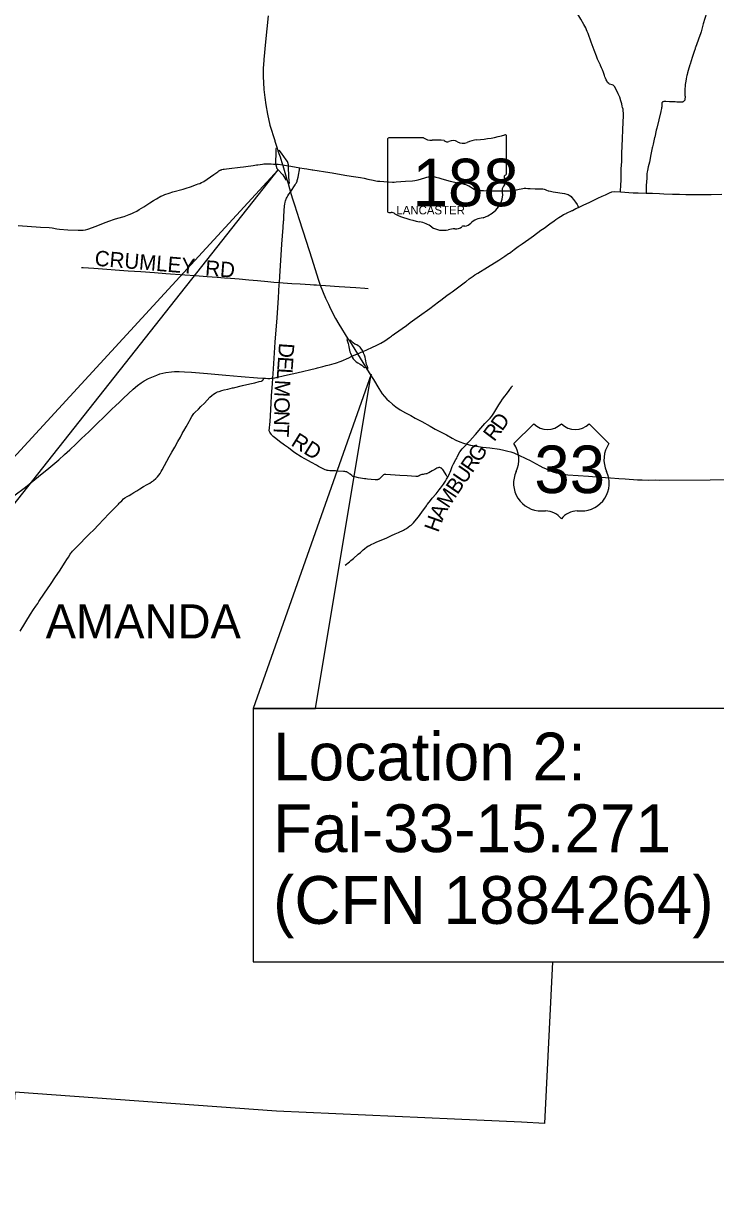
# Model space of a CAD drawing. Extents: x 1761803 to 2441803, y 509895 to 949895.
# Drawn here: x 1904079 to 1944652, y 661208 to 729125 of the extents above; entities that cross this region are included whole.
import ezdxf

# ---------------------------------------------------------------- set-up
doc = ezdxf.new("R2010")
doc.units = 0
for name, color, linetype in [('GM_X_County', 7, 'Continuous'), ('GM_X_County_Road', 7, 'Continuous'), ('GM_X_County_Road_Text', 7, 'Continuous'), ('GM_X_Minor_Lake', 7, 'Continuous'), ('GM_X_Minor_River_Text', 7, 'Continuous'), ('GM_X_State_Location', 7, 'Continuous'), ('GM_X_Township_Road', 7, 'Continuous'), ('GM_X_US_Location', 7, 'Continuous')]:
    doc.layers.add(name, color=color, linetype=linetype)

msp = doc.modelspace()

# ---------------------------------------------------------------- linework, layer by layer
at = {"layer": 'GM_X_County'}
msp.add_lwpolyline([(1935079, 674149), (1934625, 664674), (1933260, 664759), (1929353, 664934), (1918913, 665413), (1903591, 666509), (1903235, 661208)], dxfattribs=at)
at = {"layer": 'GM_X_County_Road'}
for points in [[(1919338, 717595), (1919345, 717702), (1919351, 717796), (1919373, 718129), (1919394, 718424), (1919403, 718522), (1919420, 718635), (1919445, 718730), (1919461, 718776), (1919480, 718821), (1919507, 718881), (1919539, 718938), (1919581, 719008), (1919645, 719104), (1919733, 719238), (1919934, 719542), (1920014, 719666), (1920057, 719737), (1920080, 719780), (1920120, 719871), (1920137, 719918), (1920150, 719965), (1920182, 720110), (1920281, 720657)], [(1928945, 702538), (1928918, 702572), (1928899, 702598), (1928857, 702668), (1928691, 702929), (1928654, 702983), (1928634, 703009), (1928611, 703033), (1928585, 703055), (1928572, 703064), (1928557, 703073), (1928527, 703087), (1928494, 703096), (1928461, 703099), (1928444, 703099), (1928428, 703097), (1928395, 703090), (1928363, 703080), (1928317, 703061), (1928258, 703032), (1928187, 702993), (1928032, 702900), (1927933, 702842), (1927833, 702787), (1927747, 702745), (1927724, 702736), (1927696, 702729), (1927663, 702723), (1927570, 702710), (1927503, 702701), (1927426, 702686), (1927368, 702664), (1927331, 702647), (1927267, 702614), (1927212, 702591), (1927190, 702584), (1927171, 702581), (1927149, 702579), (1927071, 702580), (1926581, 702607), (1926139, 702637), (1925861, 702658), (1925321, 702694), (1925272, 702696), (1925255, 702695), (1925238, 702693), (1925222, 702688), (1925193, 702676), (1925166, 702651), (1925130, 702617), (1925051, 702533), (1924994, 702475), (1924958, 702442), (1924932, 702422), (1924919, 702414), (1924905, 702406), (1924890, 702400), (1924875, 702395), (1924859, 702391), (1924843, 702389), (1924811, 702386), (1924779, 702386), (1924697, 702390), (1924468, 702406), (1924256, 702422), (1924159, 702432), (1924078, 702443), (1923723, 702507), (1923498, 702549), (1923451, 702560), (1923422, 702569), (1923402, 702576), (1923384, 702585), (1923366, 702596), (1923325, 702629), (1923233, 702711), (1923202, 702738), (1923164, 702769), (1923124, 702798), (1923096, 702815), (1923066, 702829), (1923035, 702841), (1923003, 702850), (1922970, 702857), (1922921, 702864), (1922839, 702872), (1922529, 702896), (1922381, 702905), (1922271, 702908), (1922152, 702911), (1922038, 702917), (1921940, 702925), (1921881, 702933), (1921844, 702942), (1921768, 702969), (1921579, 703068), (1921385, 703165), (1921253, 703234), (1920965, 703394), (1920785, 703497), (1920357, 703735), (1920215, 703816), (1920146, 703860), (1920000, 703965), (1919842, 704079), (1919612, 704253), (1919379, 704418), (1919093, 704634), (1918877, 704802), (1918713, 704927), (1918665, 704973), (1918637, 705002), (1918615, 705029), (1918568, 705105), (1918532, 705175), (1918493, 705250), (1918539, 705796), (1918562, 706136), (1918605, 706872), (1918625, 707298), (1918678, 708032), (1918699, 708334), (1918732, 708884), (1918753, 709186), (1918847, 710445), (1918948, 711872), (1919032, 713032), (1919080, 713829), (1919088, 713938), (1919113, 714284), (1919239, 716183), (1919307, 717164), (1919333, 717524), (1919338, 717595)], [(1907498, 714821), (1907511, 714822), (1907536, 714822), (1907587, 714821), (1908215, 714776), (1910225, 714627), (1910979, 714573), (1911774, 714517), (1912436, 714472), (1913556, 714396), (1914161, 714352), (1914863, 714293), (1915440, 714253), (1915874, 714219), (1916221, 714195), (1916727, 714149), (1917296, 714096), (1917801, 714053), (1918406, 713999), (1918764, 713966), (1919088, 713938), (1919302, 713922), (1919809, 713888), (1920299, 713858), (1920595, 713840), (1920888, 713819), (1921097, 713806)], [(1921097, 713806), (1921252, 713796), (1921478, 713782), (1921784, 713763)], [(1921784, 713763), (1922587, 713712), (1923567, 713641), (1924083, 713599), (1924283, 713581)], [(1930581, 705043), (1930893, 705401), (1931131, 705671), (1931428, 706000), (1931522, 706114), (1931641, 706292), (1931874, 706668), (1931943, 706780), (1932061, 706957), (1932165, 707104), (1932302, 707288), (1932381, 707393), (1932545, 707616), (1932681, 707801), (1932711, 707840), (1932732, 707863), (1932766, 707894)], [(1929423, 703567), (1929472, 703658), (1929510, 703733), (1929663, 704015), (1929803, 704191), (1929941, 704346), (1930060, 704473), (1930132, 704557), (1930235, 704672), (1930399, 704836), (1930557, 705015), (1930581, 705043)], [(1922946, 697377), (1923196, 697583), (1923278, 697650), (1923423, 697772), (1923706, 698022), (1923831, 698129), (1923990, 698271), (1924077, 698346), (1924205, 698447), (1924316, 698517), (1924365, 698544), (1924431, 698578), (1924509, 698614), (1924595, 698653), (1924804, 698744), (1925044, 698846), (1925380, 698988), (1925662, 699111), (1925877, 699209), (1926072, 699298), (1926350, 699431), (1926423, 699469), (1926535, 699538), (1926629, 699604), (1926735, 699682), (1926800, 699733), (1926897, 699822), (1926942, 699869), (1927018, 699955), (1927228, 700208), (1927436, 700483), (1927697, 700861), (1927746, 700927), (1927852, 701064), (1927938, 701173), (1928040, 701301), (1928261, 701565), (1928437, 701786), (1928527, 701898), (1928702, 702136), (1928776, 702245), (1928811, 702301), (1928877, 702414), (1928945, 702538), (1929007, 702660), (1929050, 702755), (1929082, 702825), (1929127, 702930), (1929217, 703159), (1929250, 703233), (1929293, 703327), (1929423, 703567)]]:
    msp.add_lwpolyline(points, dxfattribs=at)
at = {"layer": 'GM_X_County_Road_Text'}
for p, q in [((1933982, 705665), (1932822, 704504)), ((1938391, 704504), (1937231, 705665)), ((1934446, 700560), (1934679, 700560)), ((1936535, 700560), (1936767, 700560))]:
    msp.add_line(p, q, dxfattribs=at)
for centre, radius, start, end in [((1934795, 706493), 1160, 225.573, 314.427), ((1936419, 706493), 1160, 225.573, 314.427), ((1931492, 703573), 1624, 334.54712, 35.00093), ((1939721, 703573), 1624, 144.99907, 205.45288), ((1934428, 702184), 1624, 154.83192, 270.63826), ((1936785, 702184), 1624, 269.36174, 25.16808), ((1934679, 699400), 1160, 36.8699, 90), ((1936535, 699400), 1160, 90, 143.1301)]:
    msp.add_arc(centre, radius, start, end, dxfattribs=at)
at = {"layer": 'GM_X_Minor_Lake'}
for points in [[(1944280, 730414), (1944229, 730220), (1944097, 729708), (1943914, 729080), (1943789, 728628), (1943751, 728500), (1943717, 728407), (1943533, 727911), (1943457, 727699), (1943451, 727680)], [(1937895, 726660), (1937859, 726740), (1937824, 726819), (1937729, 727027), (1937655, 727193), (1937523, 727538), (1937466, 727705), (1937355, 728009), (1937170, 728513), (1937121, 728642), (1937079, 728734), (1937028, 728851), (1936925, 729051), (1936754, 729363), (1936573, 729655), (1936402, 729942)], [(1943434, 727630), (1943377, 727465), (1943270, 727111), (1943147, 726721)], [(1943451, 727680), (1943434, 727630)], [(1943147, 726721), (1943135, 726684), (1943031, 726356), (1942989, 726216), (1942964, 726130), (1942950, 726066), (1942931, 725979), (1942908, 725870), (1942888, 725739), (1942874, 725641), (1942864, 725540)], [(1938264, 725742), (1938263, 725744), (1938234, 725802), (1938188, 725909), (1938156, 725982), (1938128, 726059), (1938069, 726247), (1938011, 726400), (1937964, 726505), (1937897, 726654), (1937895, 726660)], [(1939238, 723728), (1939240, 723880), (1939234, 723979), (1939220, 724081), (1939194, 724190), (1939170, 724272), (1939140, 724410), (1939095, 724577), (1939028, 724793), (1938988, 724879), (1938937, 724983), (1938887, 725085), (1938820, 725213), (1938735, 725394), (1938682, 725464), (1938642, 725489), (1938571, 725513), (1938423, 725554), (1938379, 725594), (1938314, 725661), (1938264, 725742)], [(1942859, 725487), (1942851, 725399), (1942844, 725318), (1942840, 725236), (1942839, 725170), (1942839, 725170)], [(1942864, 725540), (1942859, 725487)], [(1942839, 725170), (1942839, 725039), (1942843, 724892), (1942847, 724830), (1942847, 724745), (1942846, 724712), (1942841, 724661), (1942835, 724635), (1942829, 724620), (1942814, 724592), (1942786, 724557), (1942766, 724538), (1942741, 724522), (1942726, 724516), (1942695, 724507), (1942661, 724501), (1942629, 724498), (1942596, 724498), (1942367, 724509), (1942265, 724513)], [(1941948, 724525), (1941937, 724525), (1941724, 724530), (1941641, 724532), (1941608, 724530), (1941574, 724526), (1941558, 724522), (1941542, 724516), (1941527, 724508), (1941513, 724497), (1941502, 724484), (1941493, 724470), (1941485, 724441), (1941481, 724415), (1941483, 724368), (1941482, 724249), (1941480, 724212), (1941475, 724181), (1941465, 724128), (1941430, 723977), (1941426, 723960)], [(1942265, 724513), (1942052, 724521), (1941948, 724525)], [(1939111, 720208), (1939115, 720603), (1939142, 721031), (1939153, 721472), (1939168, 721958), (1939185, 722340), (1939212, 722924), (1939219, 723285), (1939224, 723384)], [(1939224, 723384), (1939237, 723634), (1939238, 723728)], [(1941426, 723960), (1941191, 722977), (1941163, 722856)], [(1941163, 722856), (1941070, 722446), (1941069, 722439), (1940986, 722041), (1940938, 721877), (1940925, 721828), (1940840, 721426)], [(1940840, 721426), (1940761, 720979), (1940691, 720703), (1940650, 720504), (1940632, 720412), (1940614, 720299), (1940602, 720056), (1940581, 719621), (1940575, 719172)], [(1915688, 720544), (1915706, 720550), (1915789, 720570), (1915849, 720581), (1915979, 720598), (1916305, 720636), (1916632, 720668), (1916782, 720684), (1916975, 720705), (1917121, 720724), (1917559, 720791), (1917754, 720821), (1917821, 720832)], [(1917821, 720832), (1917965, 720855), (1918094, 720873), (1918176, 720882), (1918261, 720887), (1918345, 720887), (1918454, 720886), (1918552, 720883)], [(1918552, 720883), (1918597, 720882), (1918746, 720877), (1918843, 720871), (1918866, 720870), (1919024, 720864), (1919264, 720835)], [(1918552, 720883), (1918597, 720882), (1918746, 720877), (1918843, 720871), (1918866, 720870), (1919024, 720864), (1919264, 720835)], [(1919264, 720835), (1919623, 720779), (1919760, 720747), (1920281, 720657), (1920542, 720616)], [(1920542, 720616), (1920689, 720593), (1921010, 720545)], [(1903783, 717268), (1905088, 717174), (1905608, 717153), (1905784, 717130), (1906044, 717090), (1906212, 717065), (1906700, 717032), (1907291, 717001), (1907587, 716995), (1907735, 717020), (1907861, 717052), (1908353, 717238), (1908688, 717365), (1908943, 717468), (1909093, 717527), (1909433, 717643), (1909627, 717715), (1909988, 717812), (1910281, 717912), (1910444, 717980), (1910553, 718029), (1910732, 718121), (1910882, 718204), (1911007, 718284), (1911151, 718377), (1911373, 718531), (1911497, 718609), (1911714, 718749), (1911882, 718844), (1912135, 718986), (1912255, 719039), (1912376, 719090), (1912622, 719179), (1912852, 719240), (1913445, 719405), (1913692, 719482), (1913812, 719517), (1913932, 719562), (1914181, 719650), (1914234, 719675), (1914325, 719709), (1914426, 719740), (1914526, 719786), (1914621, 719835), (1914655, 719860), (1915242, 720271), (1915473, 720428), (1915538, 720470), (1915570, 720489), (1915598, 720505), (1915618, 720515), (1915636, 720524), (1915659, 720533), (1915688, 720544)], [(1921010, 720545), (1921051, 720539), (1922046, 720376), (1922183, 720354), (1922914, 720232), (1923285, 720174), (1923834, 720082), (1924060, 720042), (1924269, 719997), (1924571, 719924), (1924744, 719891), (1924830, 719880), (1924977, 719865), (1925206, 719846), (1925484, 719826), (1925714, 719817), (1925813, 719819), (1925932, 719829), (1926483, 719864), (1926876, 719890), (1927023, 719911), (1927214, 719959), (1927607, 720076), (1927733, 720112), (1927812, 720131), (1927860, 720141), (1927908, 720148), (1927957, 720151), (1928006, 720151), (1928055, 720148), (1928120, 720141), (1928184, 720130), (1928248, 720116), (1928422, 720067), (1928607, 720014), (1929084, 719882), (1929365, 719822), (1929573, 719779), (1929746, 719738), (1929868, 719711)], [(1939071, 719246), (1939096, 719681), (1939106, 719895), (1939110, 720137), (1939111, 720208)], [(1929868, 719711), (1929890, 719706), (1929959, 719689), (1930040, 719662), (1930132, 719619), (1930178, 719592), (1930280, 719534), (1930401, 719458), (1930491, 719407), (1930559, 719373), (1930649, 719348), (1930739, 719334), (1930882, 719329), (1931045, 719320), (1931227, 719314), (1931486, 719311), (1931999, 719307), (1932450, 719304), (1932651, 719302), (1932773, 719309), (1932845, 719326)], [(1932845, 719326), (1932855, 719328), (1932975, 719359), (1933054, 719379), (1933123, 719395), (1933257, 719428), (1933342, 719446), (1933428, 719457), (1933528, 719458), (1933642, 719449), (1933775, 719439), (1934069, 719425), (1934364, 719417), (1934524, 719416), (1934596, 719399), (1934652, 719376), (1934727, 719342), (1934832, 719311), (1934874, 719303), (1934968, 719286), (1935130, 719256), (1935784, 719143), (1935917, 719115), (1935994, 719086), (1936054, 719060), (1936107, 719026), (1936174, 718971), (1936226, 718912), (1936307, 718802), (1936429, 718638), (1936526, 718507), (1936577, 718424), (1936617, 718337)], [(1913839, 705884), (1913956, 706095), (1914031, 706205), (1914083, 706273), (1914139, 706332), (1914344, 706524), (1914494, 706684), (1914692, 706876), (1915013, 707219), (1915127, 707327), (1915220, 707404), (1915316, 707461), (1915386, 707504), (1915461, 707535), (1915551, 707563), (1915707, 707606), (1915850, 707643), (1916073, 707695), (1916337, 707759), (1916404, 707776), (1916918, 707898), (1917346, 707999), (1917644, 708065), (1917907, 708130), (1918034, 708162), (1918050, 708169), (1918065, 708176), (1918078, 708183), (1918091, 708192), (1918102, 708202), (1918113, 708214), (1918123, 708226), (1918132, 708239), (1918140, 708253), (1918145, 708263), (1918150, 708280), (1918152, 708300), (1918153, 708338)], [(1913458, 705196), (1913483, 705243), (1913616, 705475), (1913794, 705803), (1913839, 705884)], [(1912218, 702965), (1912218, 702965), (1912362, 703228), (1912500, 703471), (1912634, 703719), (1912792, 704006), (1912956, 704291), (1913143, 704625), (1913290, 704889), (1913399, 705085), (1913458, 705196)], [(1909707, 701013), (1909744, 701051), (1909848, 701157), (1909963, 701261), (1910041, 701317), (1910165, 701396), (1910281, 701463), (1910442, 701562), (1910556, 701632), (1910730, 701735), (1910910, 701849), (1911136, 701988), (1911340, 702104), (1911488, 702194), (1911604, 702263), (1911664, 702305), (1911712, 702345), (1911847, 702466), (1911939, 702557), (1912016, 702652), (1912093, 702757), (1912167, 702878), (1912218, 702965)], [(1904510, 694510), (1904692, 694784), (1904829, 694988), (1904931, 695140), (1904979, 695210), (1905004, 695246), (1905327, 695737), (1905673, 696257), (1905968, 696699), (1906197, 697036), (1906545, 697557), (1906644, 697712), (1906724, 697850), (1906828, 698027), (1906872, 698089), (1906910, 698133), (1906970, 698194), (1907162, 698393), (1907308, 698544), (1907411, 698644), (1907730, 698981), (1908008, 699262), (1908169, 699419), (1908526, 699793), (1908744, 700021), (1909158, 700447), (1909508, 700806), (1909659, 700962), (1909707, 701013)], [(1903899, 693520), (1904510, 694510)]]:
    msp.add_lwpolyline(points, dxfattribs=at)
at = {"layer": 'GM_X_Minor_River_Text'}
for points in [[(1918432, 729548), (1918276, 728038), (1918174, 727001), (1918170, 726949)], [(1918170, 726949), (1918154, 726721), (1918142, 726477), (1918142, 725985), (1918154, 725657), (1918179, 725236), (1918226, 724777), (1918285, 724336), (1918391, 723790), (1918533, 723144), (1918811, 722262)], [(1918811, 722262), (1918825, 722218), (1918947, 721811), (1919004, 721643), (1919059, 721493)], [(1918811, 722262), (1918825, 722218), (1918947, 721811), (1919004, 721643), (1919059, 721493)], [(1919059, 721493), (1919096, 721394)], [(1919059, 721493), (1919096, 721394)], [(1919096, 721394), (1919129, 721304), (1919264, 720835), (1919279, 720785)], [(1919096, 721394), (1919129, 721304), (1919264, 720835), (1919279, 720785)], [(1919279, 720785), (1919522, 719978), (1919594, 719742), (1919684, 719443), (1919733, 719238), (1919840, 718899), (1919978, 718478), (1920245, 717631), (1920651, 716365), (1920979, 715323), (1921355, 714126), (1921478, 713782), (1921792, 713027), (1921954, 712662), (1922079, 712402), (1922382, 711828), (1922571, 711499), (1923105, 710641), (1923185, 710513), (1923661, 709759)], [(1937923, 718964), (1937985, 718994), (1938181, 719078), (1938430, 719199), (1938558, 719250)], [(1938558, 719250), (1938732, 719259), (1939071, 719246)], [(1936238, 718155), (1936256, 718164), (1936458, 718266), (1936617, 718337), (1936913, 718481), (1937227, 718627), (1937542, 718781), (1937821, 718914), (1937923, 718964)], [(1939071, 719246), (1939071, 719246), (1939819, 719197)], [(1939819, 719197), (1940110, 719187), (1940575, 719172)], [(1940575, 719172), (1940575, 719172), (1940733, 719166)], [(1940733, 719166), (1940807, 719163), (1940937, 719164), (1941358, 719147), (1941606, 719129), (1942106, 719106)], [(1942106, 719106), (1942521, 719105), (1942902, 719100), (1943608, 719099), (1943814, 719097), (1944373, 719101), (1945012, 719109)], [(1935447, 717741), (1935644, 717863), (1935736, 717914), (1935881, 717980), (1935907, 717993)], [(1935907, 717993), (1936238, 718155)], [(1934591, 717125), (1934936, 717379), (1935180, 717554), (1935280, 717625), (1935447, 717741)], [(1932847, 715874), (1932919, 715927), (1933079, 716041), (1933310, 716198), (1933697, 716482), (1933974, 716674), (1934411, 716994), (1934591, 717125)], [(1932557, 715661), (1932639, 715720), (1932847, 715874)], [(1930020, 714005), (1930206, 714145), (1930431, 714310), (1930540, 714382), (1930710, 714483), (1931272, 714839), (1931934, 715243), (1932302, 715479), (1932515, 715632)], [(1932515, 715632), (1932557, 715661)], [(1925809, 710916), (1925835, 710935), (1926525, 711429), (1926746, 711593), (1927302, 711991), (1927893, 712420), (1928403, 712799), (1928537, 712900), (1928904, 713175), (1929088, 713313), (1929207, 713401), (1929365, 713518), (1929981, 713976), (1930020, 714005)], [(1924720, 710237), (1925024, 710380), (1925255, 710519), (1925536, 710717), (1925646, 710804), (1925714, 710850), (1925809, 710916)], [(1923331, 709614), (1923661, 709759)], [(1923331, 709614), (1923661, 709759)], [(1923661, 709759), (1923979, 709901), (1924163, 709983)], [(1923661, 709759), (1923979, 709901), (1924163, 709983)], [(1923661, 709759), (1924135, 708993), (1924153, 708965), (1924213, 708867), (1924590, 708258), (1924915, 707731), (1925009, 707583), (1925115, 707422), (1925378, 707112), (1925519, 706978), (1925704, 706820), (1925903, 706656), (1926162, 706481), (1926470, 706313), (1926777, 706140), (1927049, 705996), (1927426, 705789), (1927911, 705525), (1928216, 705357), (1928872, 705013), (1929201, 704824), (1929424, 704713), (1929664, 704605), (1929878, 704531), (1930060, 704473), (1930282, 704414), (1930511, 704373), (1930994, 704296), (1931418, 704245), (1931989, 704167), (1932229, 704124), (1932472, 704067), (1932641, 704018), (1932815, 703958), (1933122, 703831), (1933520, 703630), (1933770, 703505), (1933914, 703428)], [(1924163, 709983), (1924575, 710169), (1924720, 710237)], [(1924163, 709983), (1924575, 710169), (1924720, 710237)], [(1921639, 709022), (1921777, 709056), (1921820, 709068), (1922020, 709125), (1922304, 709199)], [(1921639, 709022), (1921777, 709056), (1921820, 709068), (1922020, 709125), (1922304, 709199)], [(1922304, 709199), (1922364, 709214), (1922709, 709326), (1923153, 709532)], [(1922304, 709199), (1922364, 709214), (1922709, 709326), (1923153, 709532)], [(1923153, 709532), (1923331, 709614)], [(1923153, 709532), (1923331, 709614)], [(1903521, 701444), (1904214, 701951), (1904977, 702583), (1905576, 703071), (1906159, 703545), (1906506, 703855), (1906810, 704134), (1907176, 704489), (1907503, 704806), (1907915, 705200), (1908397, 705651), (1908840, 706080), (1909261, 706494), (1909506, 706733), (1909701, 706917), (1909934, 707142), (1910254, 707444), (1910512, 707690), (1910766, 707903), (1910999, 708070), (1911162, 708173), (1911411, 708310), (1911703, 708440), (1911900, 708516), (1912084, 708579), (1912253, 708626), (1912442, 708660), (1912757, 708705), (1912951, 708726), (1913214, 708731), (1913529, 708715), (1913929, 708681), (1914875, 708604), (1915957, 708517), (1916855, 708436), (1917799, 708361), (1918153, 708338), (1918280, 708331), (1918417, 708325), (1918533, 708324), (1918600, 708326), (1918674, 708331), (1918699, 708334), (1918792, 708348), (1918814, 708352), (1918901, 708370), (1918959, 708386)], [(1918959, 708386), (1918973, 708390), (1919301, 708463), (1919556, 708523), (1920115, 708656), (1921259, 708928), (1921311, 708942), (1921639, 709022)], [(1933914, 703428), (1934337, 703200), (1934523, 703110), (1934672, 703035), (1934879, 702941), (1935109, 702854), (1935308, 702798), (1935515, 702750), (1935757, 702704), (1935980, 702672), (1936585, 702633), (1937190, 702586), (1937896, 702535), (1938474, 702493), (1938980, 702465), (1939346, 702440), (1940055, 702390), (1940328, 702377), (1940689, 702366), (1941090, 702371), (1941335, 702365)], [(1941335, 702365), (1944315, 702389), (1946070, 702397), (1947536, 702410), (1948024, 702397), (1948432, 702344), (1948757, 702268), (1949011, 702172), (1949181, 702100), (1949323, 702041), (1949409, 702000), (1949496, 701958), (1949546, 701932), (1949837, 701778), (1949933, 701708), (1950044, 701635), (1950129, 701566), (1950206, 701504), (1950341, 701383), (1950483, 701232), (1950518, 701195)]]:
    msp.add_lwpolyline(points, dxfattribs=at)
at = {"layer": 'GM_X_State_Location'}
for points in [[(1919017, 720540), (1889047, 687958), (1893254, 687958)], [(1924456, 708567), (1917555, 688984), (1921204, 688984)], [(1917555, 674149), (1946931, 674149), (1946931, 688984), (1917555, 688984)]]:
    msp.add_lwpolyline(points, close=True, dxfattribs=at)
at = {"layer": 'GM_X_Township_Road'}
for p, q in [((1925425, 722332), (1925425, 718105)), ((1927532, 722405), (1925494, 722405)), ((1932386, 720299), (1932386, 722509)), ((1932385, 720299), (1932386, 720299))]:
    msp.add_line(p, q, dxfattribs=at)
for centre, major_axis, start_param, end_param in [((1925505, 722341), (80.6, 0), 1.712693, 3.28349), ((1928018, 722895), (782, 0), 4.042523, 4.731795), ((1928277, 720032), (2808, 0), 1.404758, 1.657858), ((1928915, 722363), (226, 0), 3.836095, 5.185415), ((1929246, 721874), (469, 0), 0.950623, 2.079405), ((1929851, 722544), (564, 0), 4.081561, 5.145723), ((1930848, 721114), (1485, 0), 1.699011, 2.107814), ((1929907, 728167), (7382, 0), 4.814394, 5.042369), ((1932309, 722519), (77.5, 0), 6.141152, 7.989035), ((1932368, 720136), (120, 0), 1.883978, 3.671073), ((1931605, 719857), (720, 0), 5.934695, 6.695948), ((1932303, 720290), (82.9, 0), 5.05454, 6.418171), ((1930320, 719092), (1846, 0), 5.101752, 6.440018), ((1932664, 719373), (524, 0), 2.387724, 3.262537), ((1925506, 718096), (81.4, 0), 3.00124, 4.508301), ((1925518, 718529), (621, 0), 4.665946, 4.897461), ((1925645, 717862), (224, 0), 0.519207, 1.627899), ((1928472, 721659), (5331, 0), 4.195997, 4.488961), ((1926882, 716207), (1668, 0), 0.823519, 1.323587), ((1929885, 717115), (159, 0), 1.147584, 2.315152), ((1929817, 717696), (597, 0), 4.937069, 5.64225), ((1931099, 716919), (1011, 0), 1.647645, 2.488434), ((1928686, 717841), (1058, 0), 4.026481, 4.996735), ((1929298, 716379), (870, 0), 1.495662, 1.94098), ((1929375, 717524), (564, 0), 4.691044, 5.507374)]:
    msp.add_ellipse(centre, major_axis=major_axis, ratio=0.8, start_param=start_param, end_param=end_param, dxfattribs=at)
at = {"layer": 'GM_X_US_Location'}
for points in [[(1918947, 721811), (1918870, 721795), (1918885, 721671), (1918885, 721562), (1918867, 720928), (1918866, 720870)], [(1919623, 720779), (1919614, 720825), (1919583, 720962), (1919553, 721030), (1919491, 721125), (1919201, 721507), (1919124, 721616), (1919091, 721668), (1919004, 721643)], [(1918866, 720870), (1918885, 720822), (1918946, 720621), (1918994, 720553), (1919283, 720239), (1919345, 720147), (1919413, 720041), (1919461, 719958), (1919522, 719978)], [(1919594, 719742), (1919674, 719762), (1919658, 719911), (1919645, 720119), (1919628, 720723), (1919623, 720779)], [(1923105, 710641), (1923030, 710602), (1923061, 710537), (1923105, 710426), (1923122, 710370), (1923141, 710290), (1923161, 710171), (1923173, 710064), (1923191, 709967), (1923219, 709882), (1923259, 709790), (1923314, 709662), (1923331, 709614)], [(1923979, 709901), (1923955, 709947), (1923859, 710094), (1923813, 710145), (1923771, 710180), (1923700, 710228), (1923614, 710279), (1923515, 710335), (1923407, 710407), (1923326, 710480), (1923259, 710554), (1923185, 710513)], [(1924213, 708867), (1924290, 708906), (1924274, 708944), (1924227, 709050), (1924199, 709132), (1924177, 709236), (1924156, 709357), (1924137, 709450), (1924117, 709558), (1924098, 709622), (1924068, 709688), (1924036, 709759), (1924004, 709845), (1923979, 709901)], [(1923331, 709614), (1923359, 709562), (1923418, 709473), (1923450, 709422), (1923482, 709382), (1923520, 709346), (1923585, 709299), (1923689, 709242), (1923824, 709164), (1923916, 709099), (1923978, 709044), (1924039, 708976), (1924068, 708948), (1924135, 708993)]]:
    msp.add_lwpolyline(points, dxfattribs=at)

# ---------------------------------------------------------------- texts
at = {"layer": 'GM_X_County_Road'}
for s, height, rotation, p in [('LANCASTER', 500, 0.00001, (1925940, 717927)), ('CRUMLEY', 900, 355.20141, (1908242, 714925)), ('RD', 900, 355.56319, (1914714, 714348)), ('D', 900, 266.12479, (1919070, 710418)), ('E', 900, 266.12678, (1919017, 709627)), ('L', 900, 266.42053, (1918971, 708951)), ('M', 900, 266.75925, (1918843, 708252)), ('O', 900, 270.41586, (1918786, 707215)), ('N', 900, 268.07587, (1918792, 706432)), ('D', 900, 54.69149, (1932132, 705190)), ('T', 900, 267.42308, (1918766, 705643)), ('RD', 900, 327.99236, (1919711, 704425)), ('R', 900, 52.88187, (1931668, 704576)), ('G', 900, 55.5483, (1930802, 703346)), ('R', 900, 55.54787, (1930384, 702737)), ('U', 900, 55.54947, (1929936, 702084)), ('B', 900, 55.54965, (1929518, 701474)), ('M', 900, 56.24495, (1928977, 700665)), ('H', 900, 70.30035, (1928392, 699258)), ('A', 900, 64.25385, (1928649, 699980)), ('AMANDA', 2000, 0.00001, (1905392, 693088))]:
    msp.add_text(s, height=height, rotation=rotation, dxfattribs=at).set_placement(p)
at = {"layer": 'GM_X_County_Road_Text'}
msp.add_text('33', height=2784.4, dxfattribs=at).set_placement((1934022, 701604))
at = {"layer": 'GM_X_State_Location'}
for s, p in [('Location 2:', (1918718, 684773)), ('Fai-33-15.271', (1918718, 680573)), ('(CFN 1884264)', (1918718, 676373))]:
    msp.add_text(s, height=2800, dxfattribs=at).set_placement(p)
at = {"layer": 'GM_X_Township_Road'}
msp.add_text('188', height=2784.4, dxfattribs=at).set_placement((1926893, 718404))

doc.saveas('drawing.dxf')
